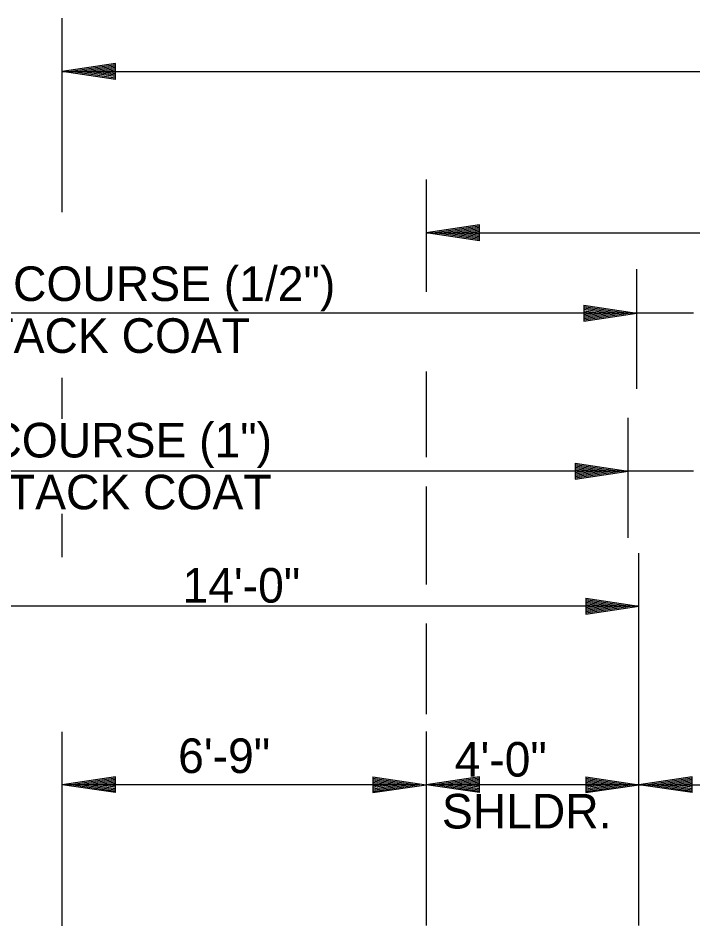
# Model space of a CAD drawing. Extents: x 6848689 to 6848907, y 1900908 to 1901005.
# Drawn here: x 6848723.43 to 6848736.11, y 1900929.57 to 1900946.63 of the extents above; entities that cross this region are included whole.
import ezdxf

# ---------------------------------------------------------------- set-up
doc = ezdxf.new("R2010")
doc.units = 0
for name, color, linetype in [('Default', 7, 'Continuous'), ('R_Draft', 7, 'Continuous'), ('R_No Plot', 7, 'Continuous')]:
    doc.layers.add(name, color=color, linetype=linetype)

msp = doc.modelspace()

# ---------------------------------------------------------------- linework, layer by layer
at = {"layer": 'Default'}
msp.add_line((6848735.099, 1900932.224), (6848757.099, 1900932.224), dxfattribs=at)
at = {"layer": 'R_Draft'}
for p, q in [((6848725.258, 1900945.778), (6848724.258, 1900945.628)), ((6848725.258, 1900945.478), (6848724.258, 1900945.628)), ((6848725.258, 1900945.753), (6848724.425, 1900945.628)), ((6848725.258, 1900945.503), (6848724.425, 1900945.628)), ((6848725.258, 1900945.728), (6848724.597, 1900945.628)), ((6848725.258, 1900945.529), (6848724.597, 1900945.628)), ((6848725.258, 1900945.703), (6848724.764, 1900945.628)), ((6848725.258, 1900945.554), (6848724.764, 1900945.628)), ((6848725.258, 1900945.677), (6848724.933, 1900945.628)), ((6848725.258, 1900945.58), (6848724.933, 1900945.628)), ((6848725.258, 1900945.652), (6848725.1, 1900945.628)), ((6848725.258, 1900945.605), (6848725.1, 1900945.628)), ((6848725.258, 1900945.478), (6848725.258, 1900945.778)), ((6848732.099, 1900942.746), (6848731.099, 1900942.596)), ((6848732.099, 1900942.446), (6848732.099, 1900942.746)), ((6848732.099, 1900942.446), (6848731.099, 1900942.596)), ((6848732.099, 1900942.721), (6848731.266, 1900942.596)), ((6848732.099, 1900942.471), (6848731.266, 1900942.596)), ((6848732.099, 1900942.695), (6848731.438, 1900942.596)), ((6848732.099, 1900942.496), (6848731.438, 1900942.596)), ((6848732.099, 1900942.67), (6848731.605, 1900942.596)), ((6848732.099, 1900942.521), (6848731.605, 1900942.596)), ((6848732.099, 1900942.645), (6848731.774, 1900942.596)), ((6848732.099, 1900942.547), (6848731.774, 1900942.596)), ((6848732.099, 1900942.619), (6848731.941, 1900942.596)), ((6848732.099, 1900942.572), (6848731.941, 1900942.596)), ((6848734.06, 1900941.232), (6848735.06, 1900941.082)), ((6848734.06, 1900941.232), (6848734.06, 1900940.932)), ((6848734.06, 1900941.207), (6848734.893, 1900941.082)), ((6848734.06, 1900941.182), (6848734.721, 1900941.082)), ((6848734.06, 1900941.157), (6848734.554, 1900941.082)), ((6848734.06, 1900941.131), (6848734.385, 1900941.082)), ((6848734.06, 1900941.106), (6848734.218, 1900941.082)), ((6848734.06, 1900940.932), (6848735.06, 1900941.082)), ((6848734.06, 1900941.033), (6848734.385, 1900941.082)), ((6848734.06, 1900940.983), (6848734.721, 1900941.082)), ((6848734.06, 1900940.957), (6848734.893, 1900941.082)), ((6848734.06, 1900941.008), (6848734.554, 1900941.082)), ((6848734.06, 1900941.059), (6848734.218, 1900941.082)), ((6848733.898, 1900938.267), (6848734.898, 1900938.117)), ((6848733.898, 1900938.267), (6848733.898, 1900937.967)), ((6848733.898, 1900938.242), (6848734.731, 1900938.117)), ((6848733.898, 1900938.216), (6848734.559, 1900938.117)), ((6848733.898, 1900938.191), (6848734.393, 1900938.117)), ((6848733.898, 1900938.165), (6848734.223, 1900938.117)), ((6848733.898, 1900938.14), (6848734.056, 1900938.117)), ((6848733.898, 1900937.967), (6848734.898, 1900938.117)), ((6848733.898, 1900938.068), (6848734.223, 1900938.117)), ((6848733.898, 1900938.017), (6848734.559, 1900938.117)), ((6848733.898, 1900937.992), (6848734.731, 1900938.117)), ((6848733.898, 1900938.042), (6848734.393, 1900938.117)), ((6848733.898, 1900938.093), (6848734.056, 1900938.117)), ((6848734.099, 1900935.727), (6848735.099, 1900935.577)), ((6848734.099, 1900935.727), (6848734.099, 1900935.427)), ((6848734.099, 1900935.702), (6848734.932, 1900935.577)), ((6848734.099, 1900935.677), (6848734.76, 1900935.577)), ((6848734.099, 1900935.652), (6848734.594, 1900935.577)), ((6848734.099, 1900935.626), (6848734.424, 1900935.577)), ((6848734.099, 1900935.601), (6848734.257, 1900935.577)), ((6848734.099, 1900935.427), (6848735.099, 1900935.577)), ((6848734.099, 1900935.528), (6848734.424, 1900935.577)), ((6848734.099, 1900935.478), (6848734.76, 1900935.577)), ((6848734.099, 1900935.452), (6848734.932, 1900935.577)), ((6848734.099, 1900935.503), (6848734.594, 1900935.577)), ((6848734.099, 1900935.554), (6848734.257, 1900935.577)), ((6848725.259, 1900932.374), (6848724.259, 1900932.224)), ((6848725.259, 1900932.349), (6848724.426, 1900932.224)), ((6848725.259, 1900932.323), (6848724.598, 1900932.224)), ((6848725.259, 1900932.074), (6848725.259, 1900932.374)), ((6848730.099, 1900932.374), (6848731.099, 1900932.224)), ((6848730.099, 1900932.374), (6848730.099, 1900932.074)), ((6848730.099, 1900932.349), (6848730.932, 1900932.224)), ((6848730.099, 1900932.323), (6848730.76, 1900932.224)), ((6848732.099, 1900932.374), (6848731.099, 1900932.224)), ((6848732.099, 1900932.349), (6848731.266, 1900932.224)), ((6848732.099, 1900932.323), (6848731.438, 1900932.224)), ((6848732.099, 1900932.074), (6848732.099, 1900932.374)), ((6848734.099, 1900932.374), (6848735.099, 1900932.224)), ((6848734.099, 1900932.374), (6848734.099, 1900932.074)), ((6848734.099, 1900932.349), (6848734.932, 1900932.224)), ((6848734.099, 1900932.323), (6848734.76, 1900932.224)), ((6848736.099, 1900932.374), (6848735.099, 1900932.224)), ((6848736.099, 1900932.349), (6848735.266, 1900932.224)), ((6848736.099, 1900932.323), (6848735.438, 1900932.224)), ((6848736.099, 1900932.074), (6848736.099, 1900932.374)), ((6848725.259, 1900932.074), (6848724.259, 1900932.224)), ((6848725.259, 1900932.099), (6848724.426, 1900932.224)), ((6848725.259, 1900932.124), (6848724.598, 1900932.224)), ((6848725.259, 1900932.298), (6848724.764, 1900932.224)), ((6848725.259, 1900932.149), (6848724.764, 1900932.224)), ((6848725.259, 1900932.273), (6848724.934, 1900932.224)), ((6848725.259, 1900932.175), (6848724.934, 1900932.224)), ((6848725.259, 1900932.247), (6848725.101, 1900932.224)), ((6848725.259, 1900932.2), (6848725.101, 1900932.224)), ((6848730.099, 1900932.298), (6848730.594, 1900932.224)), ((6848730.099, 1900932.272), (6848730.424, 1900932.224)), ((6848730.099, 1900932.247), (6848730.257, 1900932.224)), ((6848730.099, 1900932.074), (6848731.099, 1900932.224)), ((6848730.099, 1900932.175), (6848730.424, 1900932.224)), ((6848730.099, 1900932.124), (6848730.76, 1900932.224)), ((6848730.099, 1900932.099), (6848730.932, 1900932.224)), ((6848730.099, 1900932.149), (6848730.594, 1900932.224)), ((6848730.099, 1900932.2), (6848730.257, 1900932.224)), ((6848732.099, 1900932.074), (6848731.099, 1900932.224)), ((6848732.099, 1900932.099), (6848731.266, 1900932.224)), ((6848732.099, 1900932.124), (6848731.438, 1900932.224)), ((6848732.099, 1900932.298), (6848731.605, 1900932.224)), ((6848732.099, 1900932.149), (6848731.605, 1900932.224)), ((6848732.099, 1900932.273), (6848731.774, 1900932.224)), ((6848732.099, 1900932.175), (6848731.774, 1900932.224)), ((6848732.099, 1900932.247), (6848731.941, 1900932.224)), ((6848732.099, 1900932.2), (6848731.941, 1900932.224)), ((6848734.099, 1900932.298), (6848734.594, 1900932.224)), ((6848734.099, 1900932.272), (6848734.424, 1900932.224)), ((6848734.099, 1900932.247), (6848734.257, 1900932.224)), ((6848734.099, 1900932.074), (6848735.099, 1900932.224)), ((6848734.099, 1900932.175), (6848734.424, 1900932.224)), ((6848734.099, 1900932.124), (6848734.76, 1900932.224)), ((6848734.099, 1900932.099), (6848734.932, 1900932.224)), ((6848734.099, 1900932.149), (6848734.594, 1900932.224)), ((6848734.099, 1900932.2), (6848734.257, 1900932.224)), ((6848736.099, 1900932.074), (6848735.099, 1900932.224)), ((6848736.099, 1900932.099), (6848735.266, 1900932.224)), ((6848736.099, 1900932.124), (6848735.438, 1900932.224)), ((6848736.099, 1900932.298), (6848735.605, 1900932.224)), ((6848736.099, 1900932.149), (6848735.605, 1900932.224)), ((6848736.099, 1900932.273), (6848735.774, 1900932.224)), ((6848736.099, 1900932.175), (6848735.774, 1900932.224)), ((6848736.099, 1900932.247), (6848735.941, 1900932.224)), ((6848736.099, 1900932.2), (6848735.941, 1900932.224))]:
    msp.add_line(p, q, dxfattribs=at)
at = {"layer": 'R_No Plot'}
for p, q in [((6848724.258, 1900942.982), (6848724.258, 1900946.628)), ((6848724.258, 1900945.628), (6848767.936, 1900945.628)), ((6848731.099, 1900943.596), (6848731.099, 1900941.484)), ((6848731.099, 1900942.596), (6848761.1, 1900942.596)), ((6848735.06, 1900939.66), (6848735.06, 1900941.914)), ((6848736.124, 1900941.082), (6848712.301, 1900941.082)), ((6848724.258, 1900939.096), (6848724.258, 1900939.871)), ((6848731.099, 1900939.99), (6848731.099, 1900938.379)), ((6848734.898, 1900936.863), (6848734.898, 1900939.117)), ((6848736.124, 1900938.117), (6848712.301, 1900938.117)), ((6848731.099, 1900937.828), (6848731.099, 1900935.987)), ((6848724.258, 1900936.497), (6848724.258, 1900937.314)), ((6848735.099, 1900932.224), (6848735.099, 1900936.577)), ((6848735.099, 1900935.577), (6848721.097, 1900935.577)), ((6848731.099, 1900935.251), (6848731.099, 1900933.547)), ((6848724.258, 1900929.571), (6848724.258, 1900933.219)), ((6848731.099, 1900933.224), (6848731.099, 1900929.576)), ((6848735.099, 1900929.576), (6848735.099, 1900932.451)), ((6848730.974, 1900932.224), (6848724.259, 1900932.224)), ((6848735.099, 1900932.224), (6848731.099, 1900932.224))]:
    msp.add_line(p, q, dxfattribs=at)

# ---------------------------------------------------------------- texts
at = {"layer": 'R_Draft'}
for s, p in [('1\'-1 1/2" ACHM SURFACE COURSE (1/2")', (6848712.718, 1900941.313)), ('220 LBS. PER SQ. YD. & TACK COAT', (6848712.718, 1900940.338)), ('1\'-2 3/4" ACHM BINDER COURSE (1")', (6848713.123, 1900938.373)), ('330 LBS. PER SQ. YD. & TACK COAT', (6848713.123, 1900937.398)), ('14\'-0"', (6848726.518, 1900935.645)), ('6\'-9"', (6848726.437, 1900932.443)), (' 4\'-0"', (6848731.395, 1900932.376)), ('SHLDR.', (6848731.395, 1900931.401))]:
    msp.add_text(s, height=0.65, dxfattribs=at).set_placement(p)

doc.saveas('drawing.dxf')
